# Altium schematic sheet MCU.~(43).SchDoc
size A3; SheetNumber: 10; SheetTotal: 11
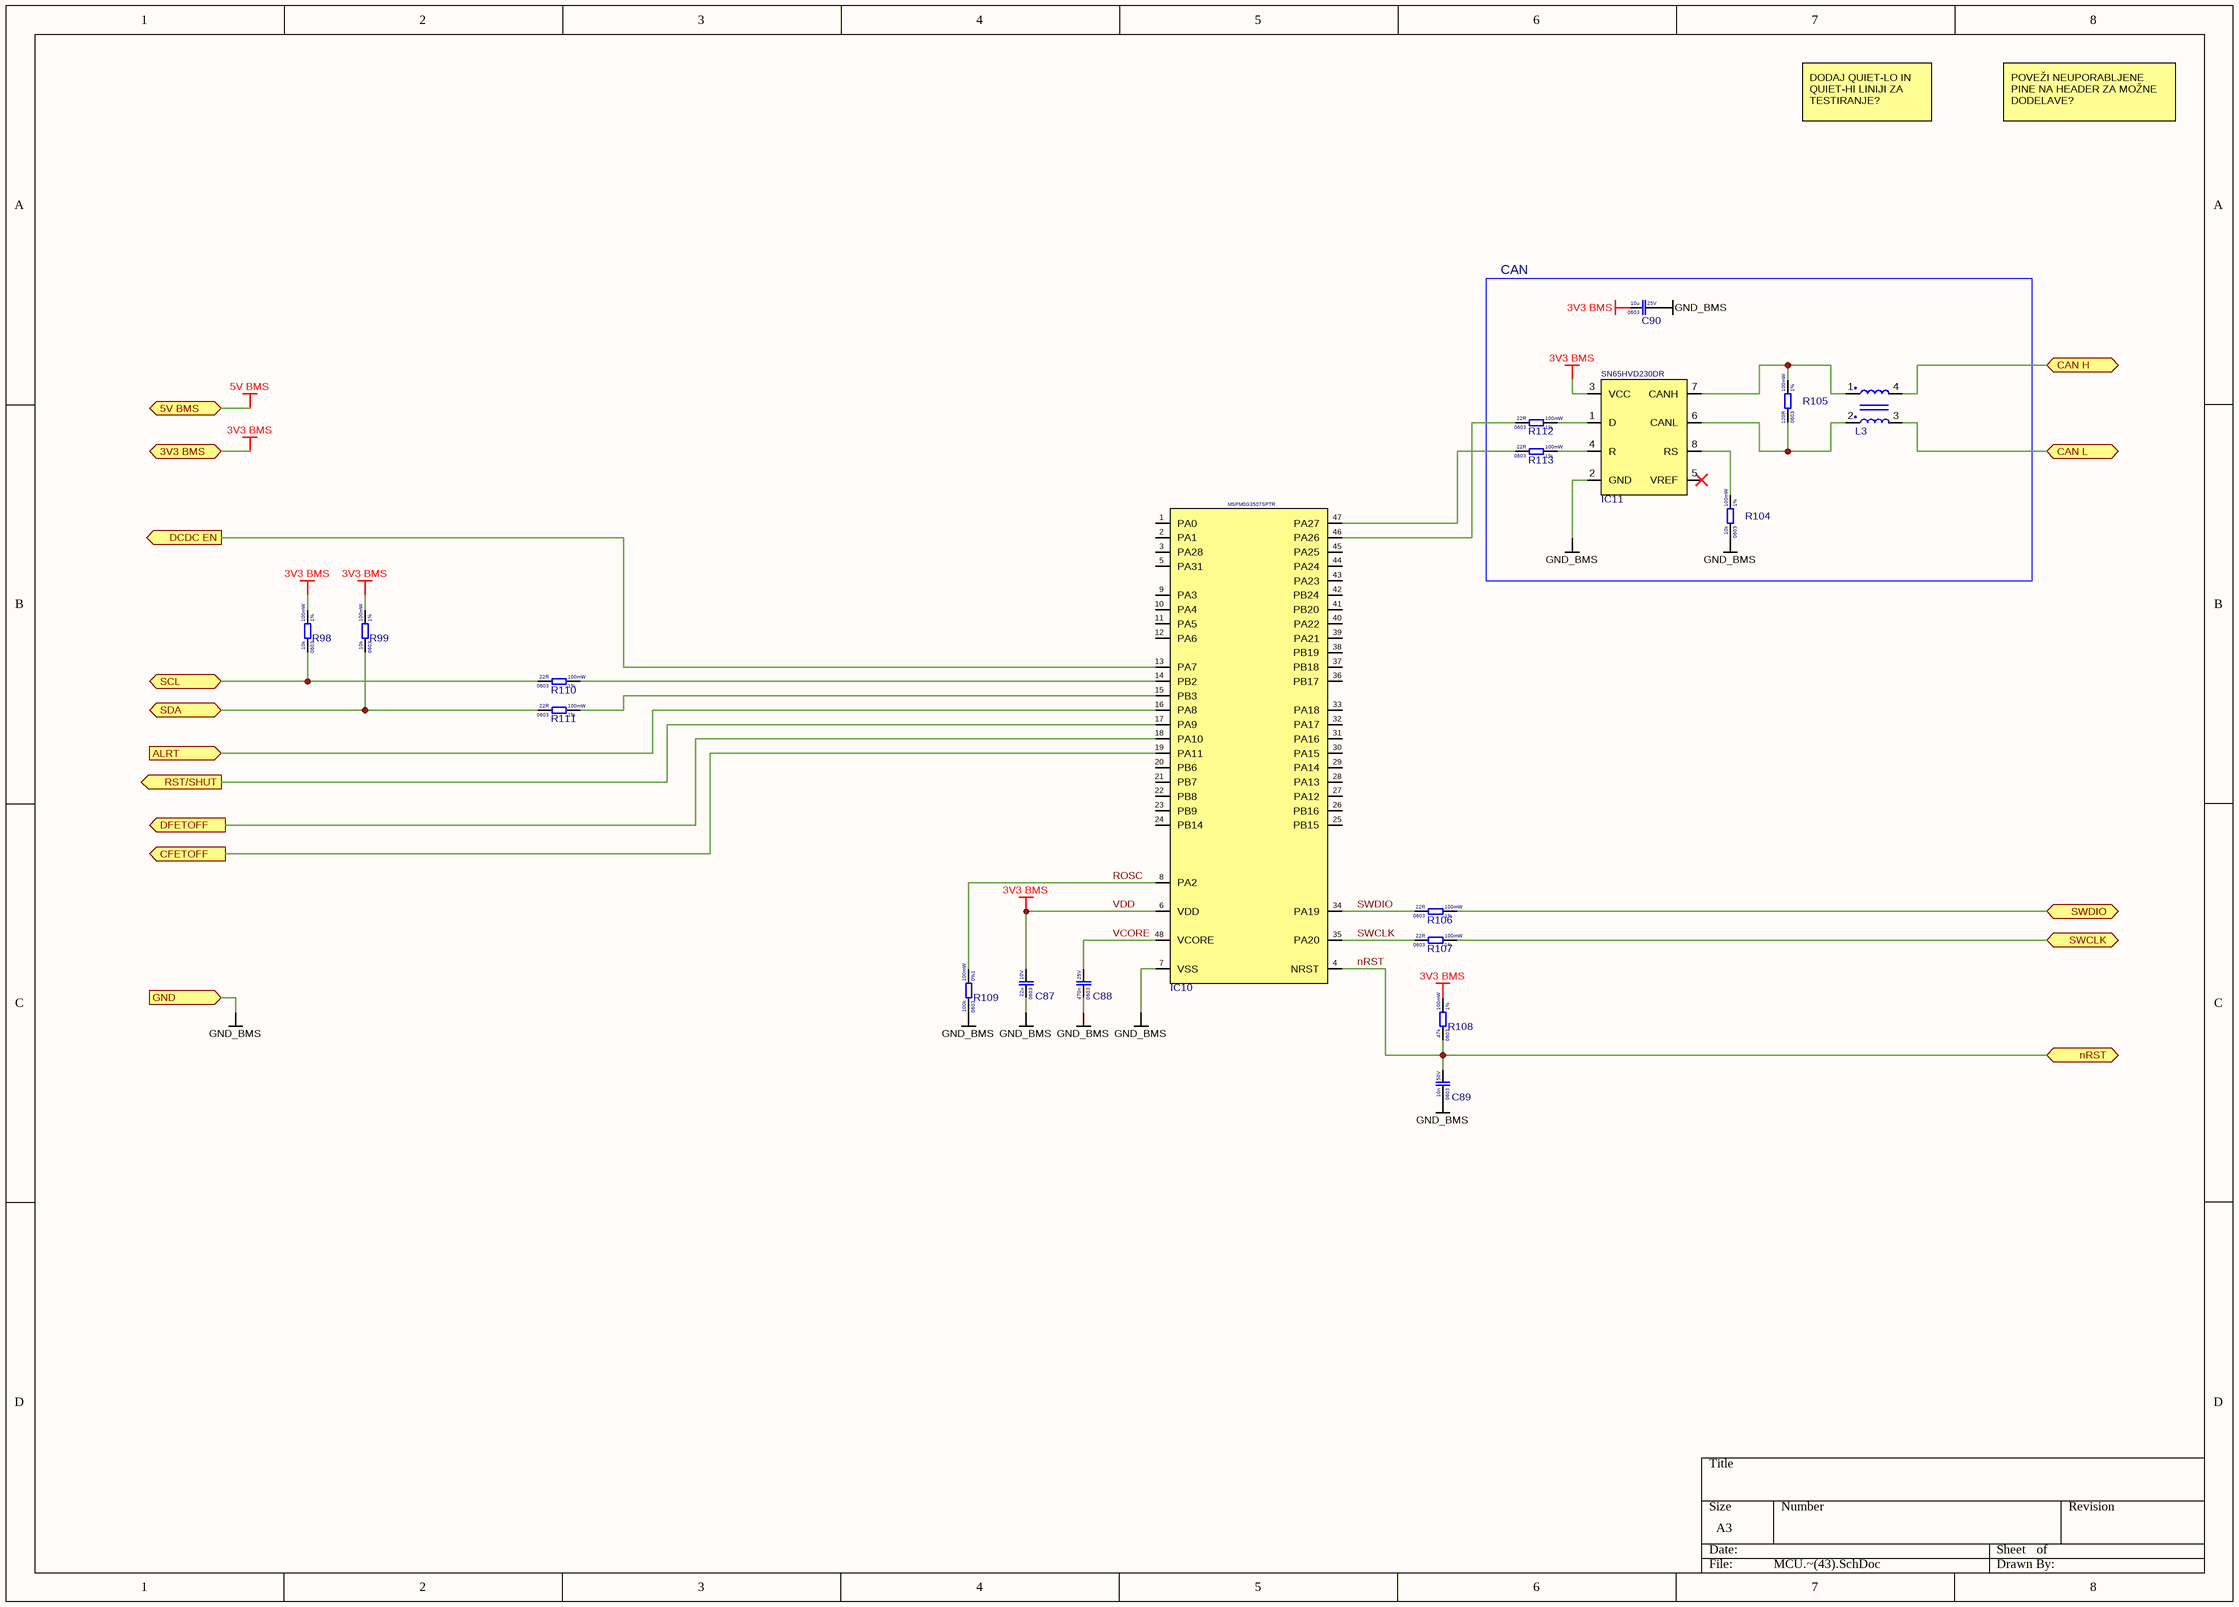
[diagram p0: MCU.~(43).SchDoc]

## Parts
C87  Voltage Rating: 10V  Case Code (Imperial): 0603  Capacitance: 22u  [CAP 0603]  (hidden comment: CGA0603X5R226M100JT)
C88  Voltage Rating: 25V  Case Code (Imperial): 0603  Capacitance: 470n  [CAP 0603]  (hidden comment: CL10B474KA8NNNC)
C89  Voltage Rating: 50V  Case Code (Imperial): 0603  Capacitance: 10n  [CAP 0603]  (hidden comment: 0603B103K500NT)
C90  Voltage Rating: 25V  Case Code (Imperial): 0603  Capacitance: 10u  [CAP 0603]  (hidden comment: CL10A106MA8NRNC)
IC10  MSPM0G3507SPTR  [LQFP-48]
IC11  SN65HVD230DR  [SOIC8]
L3  ACM2012-900-2P-T002  [ACM2012-900-2P-T002]  (value not drawn)
R98  Resistance Tolerance: 1%  Resistance: 10k  Power Rating: 100mW  Case Code (Imperial): 0603  [RES_0603]  (hidden comment: 0603WAF1002T5E)
R99  Resistance Tolerance: 1%  Resistance: 10k  Power Rating: 100mW  Case Code (Imperial): 0603  [RES_0603]  (hidden comment: 0603WAF1002T5E)
R104  Resistance Tolerance: 1%  Resistance: 10k  Power Rating: 100mW  Case Code (Imperial): 0603  [RES_0603]  (hidden comment: 0603WAF1002T5E)
R105  Resistance Tolerance: 1%  Resistance: 120R  Power Rating: 100mW  Case Code (Imperial): 0603  [RES_0603]  (hidden comment: 0603WAF1200T5E)
R106  Resistance Tolerance: 1%  Resistance: 22R  Power Rating: 100mW  Case Code (Imperial): 0603  [RES_0603]  (hidden comment: 0603WAF220JT5E)
R107  Resistance Tolerance: 1%  Resistance: 22R  Power Rating: 100mW  Case Code (Imperial): 0603  [RES_0603]  (hidden comment: 0603WAF220JT5E)
R108  Resistance Tolerance: 1%  Resistance: 47k  Power Rating: 100mW  Case Code (Imperial): 0603  [RES_0603]  (hidden comment: 0603WAF4702T5E)
R109  Resistance Tolerance: 0%1  Resistance: 100k  Power Rating: 100mW  Case Code (Imperial): 0603  [RES_0603]  (hidden comment: RT0603BRD07100KL)
R110  Resistance Tolerance: 1%  Resistance: 22R  Power Rating: 100mW  Case Code (Imperial): 0603  [RES_0603]  (hidden comment: 0603WAF220JT5E)
R111  Resistance Tolerance: 1%  Resistance: 22R  Power Rating: 100mW  Case Code (Imperial): 0603  [RES_0603]  (hidden comment: 0603WAF220JT5E)
R112  Resistance Tolerance: 1%  Resistance: 22R  Power Rating: 100mW  Case Code (Imperial): 0603  [RES_0603]  (hidden comment: 0603WAF220JT5E)
R113  Resistance Tolerance: 1%  Resistance: 22R  Power Rating: 100mW  Case Code (Imperial): 0603  [RES_0603]  (hidden comment: 0603WAF220JT5E)

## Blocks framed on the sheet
CAN: C90 IC11 L3 R104 R105 R112 R113

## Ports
3V3 BMS (bidir, see BMS[4B]), 5V BMS (bidir, see BMS[4B]), ALRT (in, see BMS[4B], BQ76952 BMS[7C]), CAN H (bidir, see BMS[4B], BMS[8B], ESD system side[2B]), CAN L (bidir, see BMS[4B], BMS[8B], ESD system side[2B]), CFETOFF (out, see BMS[4B], BQ76952 BMS[7C]), DCDC EN (out, see BMS[4B]), DFETOFF (out, see BMS[4B], BQ76952 BMS[7C]), GND (in, see BMS[4C], BQ76952 BMS[1D]), nRST (bidir, see BMS[4B], BMS[8B]), RST/SHUT (out, see BMS[4B], BQ76952 BMS[7C]), SCL (bidir, see BMS[4C], BMS[8C], BQ76952 BMS[7C]), SDA (bidir, see BMS[4C], BMS[8C], BQ76952 BMS[7C]), SWCLK (bidir, see BMS[4B], BMS[8B]), SWDIO (bidir, see BMS[4B], BMS[8B])

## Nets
GND_BMS: C87.1 C88.1 C89.1 C90.2 IC10.7(VSS) IC11.2(GND) R104.1 R109.1 ; port GND
VDD: C87.2 C90.1 IC10.6(VDD) IC11.3(VCC) R98.2 R99.2 R108.2 ; port 3V3 BMS  [also labelled 3V3 BMS]
ALRT: IC10.16(PA8) ; port ALRT
CAN H: L3.4 ; port CAN H
CAN L: L3.3 ; port CAN L
CFETOFF: IC10.19(PA11) ; port CFETOFF
DCDC EN: IC10.13(PA7) ; port DCDC EN
DFETOFF: IC10.18(PA10) ; port DFETOFF
nRST: C89.2 IC10.4(NRST) R108.1 ; port nRST
ROSC: IC10.8(PA2) R109.2
RST/SHUT: IC10.17(PA9) ; port RST/SHUT
SCL: R98.1 R110.1 ; port SCL
SDA: R99.1 R111.1 ; port SDA
SWCLK: IC10.35(PA20) R107.1
SWCLK: R107.2 ; port SWCLK  [a separate net that carries the same name]
SWDIO: IC10.34(PA19) R106.1
SWDIO: R106.2 ; port SWDIO  [a separate net that carries the same name]
VCORE: C88.2 IC10.48(VCORE)
NetIC10_14: IC10.14(PB2) R110.2
NetIC10_15: IC10.15(PB3) R111.2
NetIC10_46: IC10.46(PA26) R112.1
NetIC10_47: IC10.47(PA27) R113.1
NetIC11_1: IC11.1(D) R112.2
NetIC11_4: IC11.4(R) R113.2
NetIC11_6: IC11.6(CANL) L3.2 R105.1
NetIC11_7: IC11.7(CANH) L3.1 R105.2
NetIC11_8: IC11.8(RS) R104.2

Not connected (* = marked no-connect by the designer): IC10 1(PA0) 2(PA1) 3(PA28) 5(PA31) 9(PA3) 10(PA4) 11(PA5) 12(PA6) 20(PB6) 21(PB7) 22(PB8) 23(PB9) 24(PB14) 25(PB15) 26(PB16) 27(PA12) 28(PA13) 29(PA14) 30(PA15) 31(PA16) 32(PA17) 33(PA18) 36(PB17) 37(PB18) 38(PB19) 39(PA21) 40(PA22) 41(PB20) 42(PB24) 43(PA23) 44(PA24) 45(PA25); IC11 5(VREF)*

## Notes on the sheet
- DODAJ QUIET-LO IN QUIET-HI LINIJI ZA TESTIRANJE?
- POVEŽI NEUPORABLJENE PINE NA HEADER ZA MOŽNE DODELAVE?

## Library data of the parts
C87 = CGA0603X5R226M100JT: Cap 22uF 10V 0603 X5R; Manufacturer: HRE
C88 = CL10B474KA8NNNC: Cap 470nF 25V 0603 X7R; Manufacturer: Samsung
C89 = 0603B103K500NT: Cap 10nF 50V 0603 X7R; Manufacturer: FH
C90 = CL10A106MA8NRNC: Cap 10uF 25V 0603 X5R; Manufacturer: Samsung
IC10 = MSPM0G3507SPTR: MCU MSPM0G3507SPTR LQFP-48; Manufacturer: Texas Instruments
IC11 = SN65HVD230DR: CAN transceiver 3.3V SOIC-8 1Mbps; Manufacturer: Texas Instruments
L3 = ACM2012-900-2P-T002: CMC 90R@100MHz 190mR 400mA 50V; Manufacturer: TDK
R98 R99 R104 = 0603WAF1002T5E: Res 10k 0603 1% 100mW 75V; Manufacturer: Uni-Royal
R105 = 0603WAF1200T5E: Res 120R 0603 1% 100mW 75V; Manufacturer: Uni-Royal; Manufacturer Part Number: 0603WAF5101T5E
R106 R107 R110-R113 = 0603WAF220JT5E: Res 22R 0603 1% 100mW 75V; Manufacturer: Uni-Royal
R108 = 0603WAF4702T5E: Res 47k 0603 1% 100mW 75V; Manufacturer: Uni-Royal
R109 = RT0603BRD07100KL: Res 100k 0603 0.1% 100mW 75V 25ppm; Manufacturer: YAGEO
